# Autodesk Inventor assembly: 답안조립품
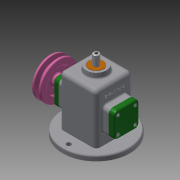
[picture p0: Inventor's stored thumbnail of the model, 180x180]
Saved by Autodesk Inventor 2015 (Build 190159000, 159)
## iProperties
Created: 2021-08
Part Number: 답안조립품
Document SubType Name: Assembly
Designer: 1048888
Author: 1048888
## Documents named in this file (16)
- C:\Users\1048888\Desktop\710806V1027\답안조립품.iam
- C:\Users\1048888\Desktop\710806V1027\V벨트풀리.ipt
- C:\Users\1048888\Desktop\710806V1027\고정핀 1.2x8.ipt
- C:\Users\1048888\Desktop\710806V1027\뒤커버.ipt
- C:\Users\1048888\Desktop\710806V1027\링크.ipt
- C:\Users\1048888\Desktop\710806V1027\멈춤나사 M3x8.ipt
- C:\Users\1048888\Desktop\710806V1027\베어링 12x32x10.ipt
- C:\Users\1048888\Desktop\710806V1027\본체.ipt
- C:\Users\1048888\Desktop\710806V1027\볼트 M4.ipt
- C:\Users\1048888\Desktop\710806V1027\부시.ipt
- C:\Users\1048888\Desktop\710806V1027\슬라이드.ipt
- C:\Users\1048888\Desktop\710806V1027\앞커버.ipt
- C:\Users\1048888\Desktop\710806V1027\오일 실 12 25 7.ipt
- C:\Users\1048888\Desktop\710806V1027\키 4x4x10.ipt
- C:\Users\1048888\Desktop\710806V1027\편심축.ipt
- C:\Users\1048888\Desktop\710806V1027\핀 5x18.ipt
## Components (3 placed, 3 different names)
1. V벨트풀리:1 — 플러쉬:2, 각도:2
2. 고정핀 1.2x8:1
3. 핀 5x18:1
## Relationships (2: Flush 1, Angle 1)
- 플러쉬:2 [Flush]: V벨트풀리:1
- 각도:2 [Angle]: V벨트풀리:1
